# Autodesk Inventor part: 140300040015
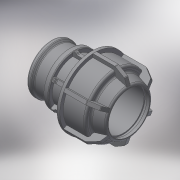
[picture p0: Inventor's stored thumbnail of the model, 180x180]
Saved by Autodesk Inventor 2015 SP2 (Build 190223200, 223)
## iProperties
Created: 2017-08
Part Number: 140300040015
Material: Generic
Description: PLASSON L.14 FEMALE ADAPTOR (SILVER) 40-1.1/2"
Document SubType Name: Modeling
Designer: KIM
Density: 1 g/cm^3
Appearance: Default
Author: KIM
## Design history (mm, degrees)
derived "140300.ipt"
feature "Solid1::140300.ipt"
tag "TaggingFeature1"
body "Solid1"
other parameters: "d2" = 73, "d4" = 15 deg, "d5" = 48.18, "d6" = 15.8994, "d9" = 44.845, "d10" = 73, "d11" = 58.2985, "d12" = 53.814, "d13" = 62.783, "d14" = 25, "d16" = 40.8, "d17" = 3.65, "d18" = 101, "d19" = 7.5, "d20" = 135 deg, "d21" = 7.5, "d22" = 53.814, "d23" = 36, "d24" = 3.65, "d25" = 65.7, "d26" = 54.75, "d27" = 3.65, "d28" = 135 deg, "d29" = 2.19, "d31" = 2, "d44" = 0.8, "d45" = 1.2, "d46" = 150 deg, "d49" = 3.65, "d50" = 0, "d51" = 0.73, "d52" = 1.46, "d53" = 45 deg, "d55" = 9.348, "d56" = 3.65, "d57" = 0, "d58" = 1.2, "d61" = 360 deg, "G_" = 44.845, "E_" = 73, "H_" = 101, "l_" = 73, "l_2" = 25, "d54" = 23.37
